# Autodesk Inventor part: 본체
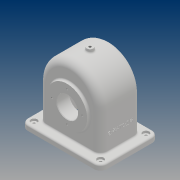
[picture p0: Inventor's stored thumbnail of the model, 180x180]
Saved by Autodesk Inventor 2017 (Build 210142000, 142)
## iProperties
Part Number: 본체
Material: 일반
Document SubType Name: Modeling
Designer: 20
Density: 1 g/cm^3
Appearance: 기본값
Author: 20
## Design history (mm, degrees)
sketch "스케치1"
  geometry: L1 (58, 13)-(58, -65); L2 (-58, 13)-(-58, -65); L3 (58, -65)-(-58, -65); A1 r 58 centre (0, 13) between (58, 13) and (-58, 13); 1 further point
  constraints: 6 end point, 2 point on circle, 2 tangent, 2 vertical, 1 centre point, 1 horizontal, 1 vertical alignment
  dimensions: "d0" = 116 diameter of A1; "d1" = 78 distance of L1.start L1.end; "d2" = 13 distance of point (0, 0) A1.centre
extrude "돌출1" new body sketch "스케치1" stored distance "d3" = 77; taper "d4" = 0 deg
sketch "스케치2"
  geometry: L1 (52, 13)-(52, -65); L2 (-58, -65)-(58, -65) reference; L3 (-52, 13)-(-52, -65); A1 r 52 centre (0, 13) between (52, 13) and (-52, 13); A2 r 58 centre (0, 13) between (58, 13) and (-58, 13) reference; 1 further point
  constraints: 4 end point, 2 point on circle, 2 point on line, 2 tangent, 2 vertical, 1 centre point, 1 concentric
  dimensions: "d5" = 104 diameter of A1
extrude "돌출2" cut sketch "스케치2" stored distance "d6" = 67; taper "d7" = 0 deg
sketch "스케치3"
  geometry: C1 r 38 at (0, 0); 1 further point
  constraints: 1 centre point, 1 coincident
  dimensions: "d8" = 76 diameter of C1
extrude "돌출3" join sketch "스케치3" distance "d9" = 5; taper "d10" = 0 deg
sketch "스케치4"
  geometry: C1 r 28 at (0, 0); 1 further point
  constraints: 1 centre point, 1 coincident
  dimensions: "d11" = 56 diameter of C1
extrude "돌출4" join sketch "스케치4" distance "d12" = 14; taper "d13" = 0 deg
sketch "스케치5"
  geometry: C1 r 38 at (0, 0); 1 further point
  constraints: 1 centre point, 1 coincident
  dimensions: "d14" = 76 diameter of C1
extrude "돌출5" join sketch "스케치5" distance "d15" = 10; taper "d16" = 0 deg
feature "면 기울기1" dims angle "d17" = 40 deg
sketch "스케치7"
  geometry: C1 r 20 at (0, 0); C2 r 38 at (0, 0) reference; 1 further point
  constraints: 1 centre point, 1 concentric
  dimensions: "d18" = 40 diameter of C1
extrude "돌출6" cut sketch "스케치7" stored distance "d19" = 0; taper "d20" = 0 deg
node "작업 평면1"
sketch "스케치8"
  geometry: C1 r 6 at (0, 0); 1 further point
  constraints: 1 centre point, 1 coincident
  dimensions: "d22" = 12 diameter of C1
extrude "돌출7" join sketch "스케치8" stored distance "d23" = 10; taper "d24" = 0 deg
sketch "스케치9"
  geometry: L1 (116, 0)-(116, -77) reference; L2 (116, -77)-(0, -77) reference; L3 (0, 0)-(0, -77) reference; L4 (0, 0)-(116, 0) reference; L5 (133, 16.5)-(-17, 16.5); L6 (-17, 16.5)-(-17, -93.5); L7 (-17, -93.5)-(133, -93.5); L8 (133, -93.5)-(133, 16.5); L9 (133, 16.5)-(-17, -93.5); L10 (-17, 16.5)-(133, -93.5); 1 further point
  constraints: 12 end point, 2 midpoint, 2 parallel, 1 horizontal, 1 perpendicular
  dimensions: "d25" = 150 distance of L7.end L6.end; "d26" = 110 distance of L6.end L5.end
extrude "돌출8" join sketch "스케치9" distance "d27" = 10; taper "d28" = 0 deg
fillet "모깎기1" dims "d29" = 12
sketch "스케치10"
  geometry: L1 (5, 16.5)-(-121, 16.5) reference; L2 (-133, 4.5)-(-133, -81.5) reference; L3 (17, -81.5)-(17, 4.5) reference; L4 (-121, -93.5)-(5, -93.5) reference; 5 further points
  constraints: 2 horizontal alignment, 2 vertical alignment
  dimensions: "d30" = 12 distance from line of L1 point (-121, 4.5); "d31" = 12 distance from line of L2 point (-121, 4.5); "d32" = 12 distance from line of L3 point (5, 4.5); "d33" = 12 distance from line of L4 point (5, -81.5)
hole "구멍1" sketch "스케치10" at (5, 4.5), (-121, 4.5), (-121, -81.5), (5, -81.5) diameter "d34" = 5; stored, may be unused: countersink angle "d38" = 90 deg, drill point angle "d40" = 0 deg; dims "d35" = 6, "d36" = 12, "d37" = 4, "d39" = 10
sketch "스케치11"
  geometry: 2 further points
  constraints: 1 coincident
hole "구멍2" sketch "스케치11" at (0, 0) diameter "d41" = 4.459; stored, may be unused: countersink angle "d45" = 90 deg, drill point angle "d47" = 0 deg; dims "d42" = 10, "d43" = 12, "d44" = 4, "d46" = 12.8
sketch "스케치12" dims "d48" = 58
  geometry: 3 further points
  constraints: 2 horizontal alignment, 1 coincident, 2 other
hole "구멍3" sketch "스케치12" at (29, 0) diameter "d49" = 3.242; stored, may be unused: countersink angle "d53" = 90 deg, drill point angle "d55" = 118 deg; dims "d50" = 8, "d51" = 12, "d52" = 4, "d54" = 10
sketch "스케치13" dims "d59" = 58
  geometry: 3 further points
  constraints: 2 vertical alignment, 1 coincident, 2 other
hole "구멍4" sketch "스케치13" at (0, -29) diameter "d60" = 3.242; stored, may be unused: countersink angle "d64" = 90 deg, drill point angle "d66" = 118 deg; dims "d61" = 8, "d62" = 12, "d63" = 4, "d65" = 10
chamfer "모따기1" distance "d70" = 1; stored, may be unused: second distance "d71" = 2, angle "d72" = 45 deg
fillet "모깎기2" dims "d73" = 13
fillet "모깎기3" dims "d74" = 8
feature "면 기울기2" dims angle "d75" = 5 deg
fillet "모깎기4" dims "d76" = 3
fillet "모깎기5" dims "d77" = 3
sketch "스케치14"
  geometry: L1 (0, -13)-(65, -13) reference; L2 (78, 68.5)-(78, -17.5) reference; 2 further points
  constraints: 1 other
  dimensions: "d78" = 38.5 distance from line of point (38, 25.5) L1; "d79" = 40 distance from line of point (38, 25.5) L2
feature "엠보싱1" sketch "스케치14" dims "d0" = 116, "d1" = 78, "d2" = 13, "d80" = 0.5, "d81" = 0
node "솔리드1"
pattern_circular "원형 패턴1" dims angle "d57" = 360 deg
pattern_circular "원형 패턴2" dims angle "d68" = 360 deg
other parameters: "d21" = 77
